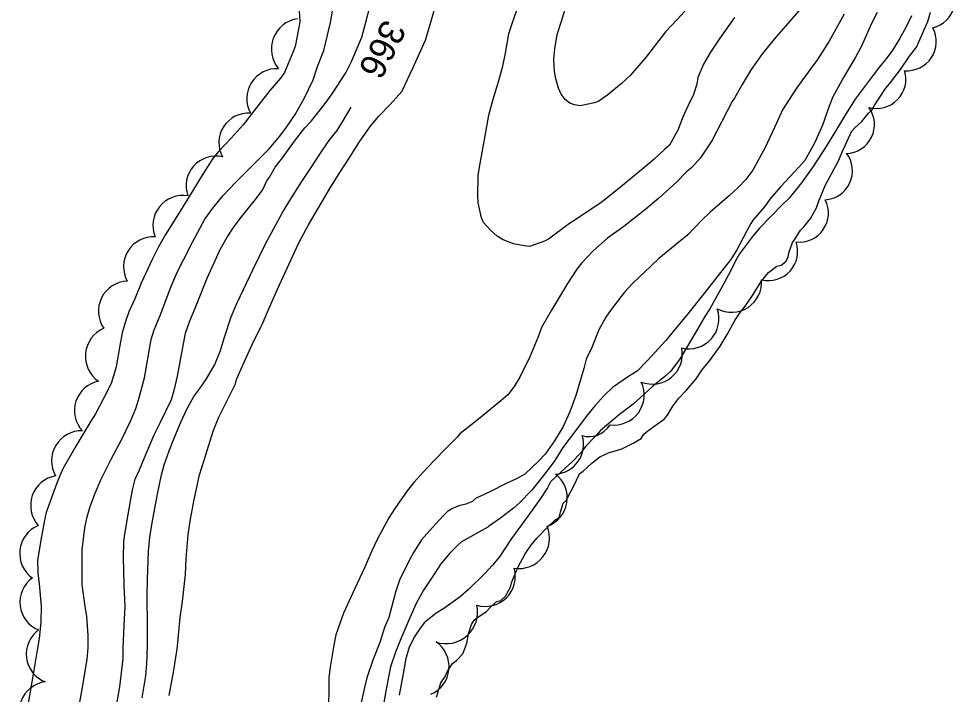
# Model space of a CAD drawing. Extents: x 287698 to 290158, y 5234163 to 5237182.
# Drawn here: x 288273 to 288381.5, y 5234876.3 to 5234954.6 of the extents above; entities that cross this region are included whole.
import ezdxf

# ---------------------------------------------------------------- set-up
doc = ezdxf.new("R2010")
doc.units = 0
for name, color, linetype in [('Niveau 1', 7, 'Continuous'), ('Niveau 2', 7, 'Continuous'), ('Niveau 4', 7, 'Continuous'), ('Niveau 44', 7, 'Continuous')]:
    doc.layers.add(name, color=color, linetype=linetype)

msp = doc.modelspace()

# ---------------------------------------------------------------- linework, layer by layer
at = {"layer": 'Niveau 1'}
for points in [[(288336.79, 5234930.85), (288334.38, 5234929.02), (288333.89, 5234928.8), (288332.18, 5234928.19), (288331.54, 5234928.24), (288330.32, 5234928.48), (288329.13, 5234928.95), (288328.41, 5234929.38), (288327.64, 5234930.07), (288326.84, 5234930.96), (288326.61, 5234931.51), (288326.23, 5234933.24), (288326.2, 5234934.1), (288326.21, 5234936.39), (288326.38, 5234937.36), (288326.91, 5234940.35), (288327.45, 5234943.4), (288327.96, 5234945.24), (288328.55, 5234947.13), (288329.08, 5234949.07), (288329.39, 5234950.59), (288329.78, 5234952.8), (288330.11, 5234953.88), (288330.79, 5234955.77)], [(288355.92, 5234954.69), (288354.22, 5234952.31), (288353.15, 5234950.69), (288352.32, 5234949.31), (288351.68, 5234947.76), (288351.54, 5234946.97), (288351.12, 5234945.65), (288350.7, 5234944.87), (288349.9, 5234943.08), (288349.37, 5234941.71), (288348.38, 5234939.91), (288347.79, 5234939.41), (288346.62, 5234938.3), (288345.16, 5234937.07), (288342.5, 5234934.88), (288340.42, 5234933.24), (288339.41, 5234932.58), (288337.43, 5234931.24), (288336.79, 5234930.85)]]:
    msp.add_lwpolyline(points, dxfattribs=at)
at = {"layer": 'Niveau 2'}
for points in [[(288280.03, 5234874.98), (288280.41, 5234877.11), (288280.96, 5234880.36), (288281.07, 5234881.68), (288281.06, 5234883.1), (288280.89, 5234885.35), (288280.72, 5234886.49), (288280.38, 5234889.01), (288280.35, 5234890.36), (288280.38, 5234893.05), (288280.66, 5234895.58), (288280.95, 5234896.85), (288281.3, 5234898.07), (288281.88, 5234899.61), (288282.54, 5234901.16), (288283.68, 5234903.46), (288284.95, 5234905.85), (288286.01, 5234908.04), (288286.58, 5234909.43), (288286.93, 5234910.52), (288287.57, 5234912.97), (288287.84, 5234914.52), (288288.37, 5234917.42), (288288.71, 5234918.51), (288289.39, 5234920.2), (288290.65, 5234923.45), (288291.42, 5234925.27), (288292.09, 5234926.65), (288293.14, 5234928.66), (288294.58, 5234931.35), (288295.5, 5234932.63), (288296.64, 5234934.03), (288298.16, 5234935.63), (288300.16, 5234937.62), (288302.01, 5234939.5), (288303.26, 5234940.95), (288304.04, 5234941.99), (288305.03, 5234943.48), (288306.06, 5234945.31), (288307.1, 5234947.5), (288307.61, 5234949.02), (288308.36, 5234950.87), (288308.57, 5234951.83), (288309.12, 5234954.13), (288309.53, 5234956.33)], [(288287.01, 5234902.32), (288287.73, 5234904.09), (288288.71, 5234906.35), (288289.42, 5234907.81), (288290.7, 5234910.45), (288291.07, 5234911.66), (288291.4, 5234913.15), (288291.71, 5234914.82), (288292.34, 5234918.14), (288292.83, 5234919.57), (288293.44, 5234921.03), (288294.86, 5234924.52), (288296.34, 5234927.83), (288297.16, 5234929.25), (288297.97, 5234930.51), (288298.82, 5234931.62), (288300.27, 5234933.41), (288301.25, 5234934.72), (288301.74, 5234935.77), (288302.08, 5234936.2), (288302.71, 5234937.35), (288303.56, 5234938.46), (288304.95, 5234940.37), (288306.14, 5234941.92), (288306.91, 5234942.74), (288308.52, 5234944.73), (288309.33, 5234945.87), (288310.9, 5234948.31), (288311.55, 5234949.6), (288312.74, 5234952.42), (288313.18, 5234954.02), (288313.74, 5234956.26)], [(288291.47, 5234882.73), (288291.73, 5234885.2), (288291.99, 5234887.05), (288292.32, 5234890.18), (288292.4, 5234891.99), (288292.63, 5234894.79), (288292.88, 5234896.37), (288293.29, 5234898.68), (288293.95, 5234901.71), (288294.48, 5234903.44), (288295.55, 5234906.77), (288296.2, 5234908.4), (288296.96, 5234909.95), (288298.13, 5234912.28), (288298.25, 5234912.77), (288298.78, 5234914), (288300.06, 5234916.82), (288301.32, 5234919.42), (288301.97, 5234920.97), (288302.97, 5234923.25), (288303.87, 5234925.16), (288305.47, 5234928.6), (288306.59, 5234930.67), (288307.73, 5234932.65), (288309.16, 5234935.1), (288310.28, 5234936.87), (288311.45, 5234938.63), (288312.54, 5234940.37), (288313.75, 5234942.13), (288314.69, 5234943.22), (288316.03, 5234944.61), (288317.38, 5234946.14), (288317.73, 5234946.85), (288318.67, 5234948.85), (288320.11, 5234952.07), (288320.66, 5234953.9), (288321.44, 5234956.61)], [(288350.64, 5234955.95), (288349.28, 5234954.46), (288347.91, 5234953.03), (288346.77, 5234951.53), (288345.55, 5234950), (288343.81, 5234947.97), (288342.81, 5234947.05), (288341.24, 5234945.76), (288340.2, 5234945.01), (288339.7, 5234944.82), (288338.03, 5234944.46), (288337.4, 5234944.57), (288336.85, 5234944.79), (288336.31, 5234945.21), (288335.84, 5234945.84), (288335.53, 5234946.51), (288335.21, 5234947.58), (288335.07, 5234948.43), (288334.98, 5234949.85), (288335.09, 5234951.07), (288335.38, 5234952.72), (288335.88, 5234954.26), (288336.57, 5234956.56)], [(288372.42, 5234955.29), (288371.79, 5234954), (288370.57, 5234951.31), (288369.91, 5234950.1), (288368.52, 5234947.77), (288367.31, 5234945.53), (288366.88, 5234944.44), (288366.1, 5234942.23), (288365.16, 5234940.14), (288364.04, 5234938.12), (288363.35, 5234937.35), (288361.28, 5234935.14), (288360, 5234933.65), (288359.38, 5234932.79), (288358.09, 5234931.25), (288357.8, 5234930.83), (288357.34, 5234929.98), (288356.2, 5234927.78), (288355.48, 5234926.69), (288354.7, 5234925.71), (288352.47, 5234922.84), (288350.35, 5234920.17), (288348.98, 5234918.52), (288347.95, 5234917.28)], [(288363.86, 5234956.06), (288362.32, 5234954.26), (288360.7, 5234952.42), (288359.17, 5234950.55), (288357.83, 5234948.68), (288356.79, 5234946.95), (288355.9, 5234945.36), (288355.65, 5234944.97)], [(288368.63, 5234955.08), (288366.89, 5234951.98), (288365.53, 5234949.84), (288364.74, 5234948.8), (288363.08, 5234946.5), (288361.46, 5234944.02), (288360.82, 5234942.55), (288359.45, 5234939.64), (288358.05, 5234937), (288357.22, 5234935.95), (288356.34, 5234935.01), (288355.32, 5234934.07), (288353.11, 5234932.15), (288352.09, 5234931.17), (288350.5, 5234929.52), (288349.46, 5234928.69), (288347.15, 5234926.78), (288346.23, 5234925.91), (288344.13, 5234923.92), (288343.19, 5234922.87), (288341.62, 5234920.89), (288341.02, 5234919.98), (288340.19, 5234918.52)], [(288376.4, 5234954.91), (288375.75, 5234953.54), (288375.03, 5234952.23), (288374.26, 5234950.96), (288373.49, 5234949.92), (288372.72, 5234949), (288371.98, 5234948.01), (288369.9, 5234945.23)], [(288355.65, 5234944.97), (288353.27, 5234940.4), (288351.99, 5234938.43), (288350.98, 5234937.33), (288350.33, 5234936.77), (288349.18, 5234935.63), (288347.16, 5234933.78), (288345.66, 5234932.52), (288343.1, 5234930.51), (288341.21, 5234929.14), (288339.55, 5234927.67), (288338.23, 5234926.29), (288337.65, 5234925.54), (288336.59, 5234923.88), (288334.7, 5234920.8), (288333.56, 5234918.79), (288333.16, 5234917.72), (288332.21, 5234915.41), (288331.06, 5234913.04), (288330.38, 5234911.96), (288329.68, 5234910.98), (288328.87, 5234910.3), (288326.26, 5234908.18), (288324.12, 5234906.48), (288323.78, 5234906.1), (288322.32, 5234904.61), (288320.29, 5234902.51), (288318.77, 5234900.84), (288318, 5234899.89), (288316.56, 5234897.84), (288315.9, 5234896.74), (288314.54, 5234894.24), (288313.92, 5234892.91), (288313.05, 5234890.95), (288311.96, 5234888.56), (288310.64, 5234885.69), (288309.73, 5234883.21), (288309.52, 5234881.99), (288309.07, 5234879.46), (288308.93, 5234878.27), (288308.94, 5234877.09), (288308.91, 5234874.7)], [(288369.9, 5234945.23), (288368.76, 5234943.46), (288367.74, 5234941.71), (288366.43, 5234939.63), (288365.01, 5234937.44), (288363.68, 5234935.54), (288362.23, 5234933.77), (288361.35, 5234932.91), (288358.84, 5234930.32), (288358, 5234929.34), (288356.5, 5234927.31), (288356.04, 5234926.53), (288355.47, 5234925.38), (288354.66, 5234923.89), (288353.05, 5234920.95), (288352.47, 5234920.08), (288351.35, 5234918.14), (288349.62, 5234915.2), (288348.48, 5234913.69), (288347.85, 5234913.11), (288346.38, 5234911.91), (288344.16, 5234909.93), (288342.59, 5234908.72), (288340.41, 5234906.87), (288339.85, 5234906.24), (288338.66, 5234905.01), (288338.15, 5234904.32), (288337.05, 5234903.14), (288336.39, 5234902.58), (288334.61, 5234900.93), (288334.25, 5234900.24), (288333.46, 5234899), (288332.66, 5234897.9), (288331.96, 5234896.95), (288330.1, 5234894.37), (288328.69, 5234892.24), (288327.89, 5234891.25), (288327.01, 5234890.3), (288325.1, 5234888.43), (288324.14, 5234887.6), (288322.25, 5234886.23), (288321.37, 5234885.71), (288319.99, 5234884.58), (288319.42, 5234883.87), (288318.91, 5234883.04), (288318.23, 5234881.76), (288317.81, 5234880.29), (288317.65, 5234879.34), (288317.09, 5234876.19)], [(288300.13, 5234925.48), (288301.61, 5234928.47), (288302.56, 5234930.27), (288303.54, 5234932.02), (288304.52, 5234933.68), (288305.81, 5234935.71), (288306.75, 5234937.1), (288308.18, 5234939.35), (288309.04, 5234940.56), (288309.88, 5234941.63), (288310.64, 5234942.82), (288311.52, 5234944.32)], [(288287.3, 5234875.89), (288287.74, 5234878.45), (288287.86, 5234879.83), (288287.94, 5234881.93), (288287.94, 5234884.21), (288287.89, 5234887.75), (288287.92, 5234889.61), (288288.03, 5234892.88), (288288.21, 5234894.52), (288288.48, 5234896.17), (288289.09, 5234899.48), (288289.54, 5234901.71), (288289.87, 5234902.88), (288290.44, 5234904.52), (288291.08, 5234906.16), (288291.78, 5234907.82), (288292.53, 5234909.43), (288293.3, 5234910.8), (288294.01, 5234911.73), (288294.75, 5234912.84), (288295.75, 5234914.49), (288296.39, 5234916.12), (288296.83, 5234917.57), (288297.62, 5234920.03), (288298.26, 5234921.56), (288299.04, 5234923.21), (288300.13, 5234925.48)], [(288340.19, 5234918.52), (288339.38, 5234916.48), (288338.74, 5234915.12), (288338.45, 5234914.05), (288337.53, 5234910.9), (288336.83, 5234909.03), (288336.03, 5234907.25), (288335.08, 5234905.67), (288333.98, 5234904.13), (288333.2, 5234903.32), (288331.62, 5234901.81), (288330.67, 5234901.27), (288329.55, 5234900.77), (288327.49, 5234899.73), (288325.92, 5234899), (288325.56, 5234898.65), (288324.79, 5234898.32), (288324, 5234898.14), (288323.24, 5234897.84), (288322.69, 5234897.47), (288322.17, 5234896.96), (288320.92, 5234895.63), (288319.68, 5234894.21), (288318.73, 5234892.75), (288318.22, 5234891.8), (288317.12, 5234889.52), (288316.61, 5234888.01), (288316.58, 5234887.81)], [(288347.95, 5234917.28), (288345.81, 5234914.93), (288344.62, 5234913.72), (288343.62, 5234913.11), (288341.78, 5234911.85), (288340.82, 5234910.9), (288339.76, 5234909.77), (288338.73, 5234908.49), (288337.74, 5234907.14), (288336.04, 5234904.88), (288335.01, 5234903.29), (288333.79, 5234901.66), (288332.41, 5234899.93), (288331.03, 5234898.49), (288330.31, 5234897.87), (288328.83, 5234896.71), (288327.42, 5234895.74), (288327.33, 5234895.68)], [(288284.18, 5234874.07), (288284.73, 5234877.18), (288285.12, 5234880.44), (288285.1, 5234881.6), (288285.25, 5234884.27), (288285.33, 5234886.49), (288285.24, 5234888.95), (288285.16, 5234892.17), (288285.19, 5234893.97), (288285.3, 5234894.85), (288285.69, 5234897.15), (288286.19, 5234900.01), (288286.51, 5234901.23), (288287.01, 5234902.32)], [(288327.33, 5234895.68), (288324.31, 5234893.98), (288323.78, 5234893.52), (288322.96, 5234892.67), (288321.91, 5234891.42), (288321.19, 5234890.35), (288319.9, 5234888.36), (288319.04, 5234886.81), (288318.33, 5234885.18), (288317.27, 5234882.75), (288316.67, 5234881.17), (288316.08, 5234879.47), (288315.88, 5234878.53), (288315.55, 5234876.66), (288315.04, 5234873.8)], [(288316.58, 5234887.81), (288315.9, 5234885.21), (288315.37, 5234884.04), (288314.82, 5234882.31), (288314.01, 5234880.26), (288313.32, 5234878.21), (288313.06, 5234877.1), (288312.24, 5234873.46)], [(288290.46, 5234876.15), (288290.94, 5234878.87), (288291.36, 5234881.53), (288291.47, 5234882.73)]]:
    msp.add_lwpolyline(points, dxfattribs=at)
at = {"layer": 'Niveau 4'}
for points in [[(288305.5, 5234955.48), (288305.59, 5234954.24), (288305.47, 5234953.55), (288305.02, 5234951.36), (288304.75, 5234950.63), (288303.78, 5234948.35), (288303.32, 5234947.68), (288302.1, 5234946.23), (288300.61, 5234944.3), (288299.03, 5234942.28), (288297.62, 5234940.72), (288296.15, 5234939.17), (288295.5, 5234938.36), (288294.33, 5234936.55), (288293.2, 5234934.68), (288291.72, 5234932.26), (288290.01, 5234929.57), (288289.19, 5234928.14), (288288.48, 5234926.66), (288287.19, 5234923.94)], [(288345.1, 5234905.93), (288345.43, 5234906.42), (288345.87, 5234906.83), (288346.84, 5234907.53), (288347.75, 5234908.18), (288348.14, 5234908.64), (288348.77, 5234909.67), (288349.48, 5234910.6), (288350.35, 5234911.52), (288351.46, 5234912.85), (288352.14, 5234913.85), (288353.07, 5234914.98), (288354.26, 5234916.64), (288355.08, 5234917.98), (288355.96, 5234919.59), (288356.57, 5234920.54), (288357.26, 5234921.43), (288358.08, 5234922.63), (288359.01, 5234924.11), (288359.83, 5234925.18), (288360.81, 5234925.9), (288361.31, 5234926), (288361.86, 5234926.45), (288362.11, 5234926.95), (288362.2, 5234927.45), (288362.63, 5234928.65), (288362.95, 5234929.06), (288363.57, 5234930.07), (288363.99, 5234930.5), (288364.73, 5234931.43), (288365.39, 5234932.65), (288365.64, 5234933.36), (288366.45, 5234935.33), (288366.89, 5234936.1), (288367.94, 5234938.11), (288368.47, 5234939.3), (288368.95, 5234940.39), (288369.46, 5234941.48), (288369.85, 5234941.92), (288370.67, 5234942.67), (288371.44, 5234943.61), (288371.81, 5234943.97), (288372.08, 5234944.47), (288373.31, 5234946.36), (288373.96, 5234947.16), (288375.12, 5234948.69), (288376.16, 5234950.21), (288376.98, 5234951.28), (288377.25, 5234951.9), (288378.31, 5234954.24), (288378.59, 5234955.32)], [(288287.19, 5234923.94), (288286.48, 5234922.13), (288285.79, 5234920.61), (288285.37, 5234919.49), (288285, 5234918.19), (288284.74, 5234916.72), (288284.3, 5234914.25), (288283.76, 5234912.42), (288283.21, 5234911.3), (288281.9, 5234908.79), (288281.36, 5234907.93), (288279.64, 5234905.06), (288278.13, 5234902.42), (288277.55, 5234901.07), (288277.01, 5234899.62), (288276.21, 5234897.36), (288275.98, 5234896.29), (288275.67, 5234894.57), (288275.21, 5234891.83), (288275.22, 5234890.39), (288275.4, 5234889.1), (288275.63, 5234886.5), (288275.57, 5234884.66), (288275.4, 5234882.76), (288275.2, 5234881.66), (288274.63, 5234878.18), (288274.12, 5234875.27)], [(288321.4, 5234875.97), (288321.92, 5234877.65), (288322.41, 5234878.35), (288322.64, 5234878.9), (288323.25, 5234879.89), (288323.73, 5234880.21), (288324.46, 5234881.01), (288324.9, 5234882.24), (288325.09, 5234883.32), (288325.44, 5234884.4), (288325.75, 5234884.89), (288326.18, 5234885.24), (288327.21, 5234885.89), (288327.57, 5234886.32), (288328.33, 5234887.07), (288328.86, 5234887.18), (288329.39, 5234887.68), (288329.98, 5234888.73), (288330.07, 5234889.23), (288330.3, 5234889.81), (288330.86, 5234891.06), (288331.66, 5234892.58), (288332.32, 5234893.56), (288333.01, 5234894.39), (288334.28, 5234895.69), (288335.1, 5234896.46), (288335.61, 5234896.8), (288335.78, 5234897.4), (288336.08, 5234898.44), (288336.47, 5234898.8), (288336.68, 5234899.31), (288337.28, 5234900.38), (288337.96, 5234901.83), (288338.38, 5234902.16), (288339.4, 5234903.08), (288340.32, 5234903.81), (288341.33, 5234904.26), (288342.86, 5234904.74), (288344.19, 5234905.4), (288345.1, 5234905.93)]]:
    msp.add_lwpolyline(points, dxfattribs=at)
at = {"layer": 'Niveau 44'}
for centre, radius, start, end in [((288378.06, 5234956.83), 3.42, 284.0957, 45.8314), ((288375.86, 5234951.94), 3.42, 265.8849, 27.3745), ((288302.92, 5234945.29), 3.49, 86.9031, 208.4285), ((288372.37, 5234947.56), 3.39, 254.645, 16.7224), ((288299.64, 5234940.19), 3.44, 86.4848, 208.3537), ((288295.85, 5234935.19), 3.45, 77.2328, 199.3426), ((288292.02, 5234930.63), 3.46, 80.5316, 202.4738), ((288285.74, 5234920.68), 3.49, 92.6575, 214.5487), ((288355.55, 5234924.06), 3.51, 242.4079, 4.3514), ((288284.27, 5234915.46), 3.53, 113.4179, 235.2348), ((288322.53, 5234885.79), 3.62, 251.2694, 13.2293), ((288277.37, 5234880.96), 3.47, 126.2406, 247.986), ((288276.57, 5234874.29), 3.5, 98.2074, 220.2421)]:
    msp.add_arc(centre, radius, start, end, dxfattribs=at)
for centre, major_axis, ratio, start_param, end_param in [((288305.81, 5234951.06), (-2.73, 2.24), 0.999963, 5.547216, 7.673662), ((288368.75, 5234942.31), (1.47, 3.03), 0.999984, 3.633115, 5.791663), ((288366.21, 5234936.94), (1.4, 3.06), 0.999984, 3.63429, 5.790488), ((288363.43, 5234932.05), (1.92, 2.76), 0.999984, 3.634607, 5.790171), ((288288.64, 5234925.83), (-2.94, 1.86), 0.999995, 5.223529, 7.347597), ((288359.86, 5234927.6), (2.27, 2.49), 0.999984, 3.63779, 5.786988), ((288350.64, 5234919.79), (2.34, 2.57), 0.996617, 3.636803, 5.787975), ((288346.4, 5234915.71), (2.66, 2.24), 0.997058, 3.636432, 5.788346), ((288282.92, 5234909.18), (-3.28, 1.06), 0.999994, 5.215926, 7.346601), ((288341.98, 5234910.97), (2.05, 2.81), 0.996141, 3.637423, 5.787355), ((288339.28, 5234909.6), (-0.69, -3.4), 0.841683, 6.174596, 7.378212), ((288280.31, 5234903.35), (-2.84, 2.02), 0.999401, 5.303444, 7.426738), ((288334.97, 5234905.26), (2.36, 2.55), 0.995036, 3.953675, 5.757826), ((288277.88, 5234898.17), (-3.11, 1.57), 0.999768, 5.348495, 7.47975), ((288333.08, 5234899.04), (2.12, 2.75), 0.99433, 4.131091, 6.286921), ((288276.63, 5234892.63), (-3.17, 1.48), 0.999963, 5.546824, 7.673165), ((288330.95, 5234894.4), (2.64, -2.34), 0.999038, 5.28046, 7.406794), ((288327.04, 5234889.97), (2.16, -2.74), 0.999695, 5.3287, 7.461134), ((288276.63, 5234886.97), (2.1, -2.76), 0.999995, 3.113797, 5.245126), ((288319.37, 5234879.51), (3.47, -0.34), 0.99946, 5.220359, 7.341588)]:
    msp.add_ellipse(centre, major_axis=major_axis, ratio=ratio, start_param=start_param, end_param=end_param, dxfattribs=at)

# ---------------------------------------------------------------- texts
at = {"layer": 'Niveau 2'}
msp.add_text('366', height=3, rotation=242.9418, dxfattribs=at).set_placement((288315.34, 5234954.66))

doc.saveas('drawing.dxf')
